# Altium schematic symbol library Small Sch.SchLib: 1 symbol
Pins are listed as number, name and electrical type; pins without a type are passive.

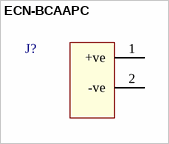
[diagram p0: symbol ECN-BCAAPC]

## ECN-BCAAPC
designator J?, comment BATTERY HOLDER AA PC PIN  (value not drawn)
Manufacturer: MPD (Memory Protection Devices); Manufacturer Part Number: BCAAPC; Internal Part Number: ECN-BCAAPC; Vendor Part Number: BCAAPC-ND; 3rd Auxiliary Field: RoHS Compliant; Temp Co: -10°C ~ 100°C; Vendor Name: Digi-Key; Component Height (mm): 13.69mm
footprint BATT_BCAAPC AA (Footprint not found)
pins: 1 +ve, 2 -ve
